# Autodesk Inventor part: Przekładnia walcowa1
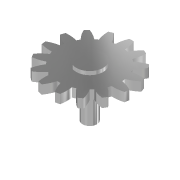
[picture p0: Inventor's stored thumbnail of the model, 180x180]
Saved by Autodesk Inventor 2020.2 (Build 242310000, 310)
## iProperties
Manager: www.cadconsulting.pl
Company: Fabian Stasiak CAD Consulting
CustomPartVersion: 1
Created: 2014-10
Part Number: Przekładnia walcowa1
Material: Steel
Document SubType Name: Modeling
Designer: F.Stasiak
Categories: <?xml version="1.0" encoding="UTF-16"?> <MemberInstance><Categories><FamilyTemplate><FamilyTemplateParameter ValueType="xs:double" Id="1" ObjectReferenceKey="da
Density: 7.85 g/cm^3
Appearance: Chrom - polerowany
Mass: 65.8697 g
Surface Area: 46.5032 cm^2
Volume: 8.39104 cm^3
Catalog Web Link: www.expertbooks.pl
Author: F.Stasiak
Subject: Zbiór ćwiczeń. Autodesk Inventor 2020. Kurs Professional
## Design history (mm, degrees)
sketch "Sketch1"
  geometry: C1 r 23.359 at (0, 0)
  constraints: 1 centre point
  dimensions: "d0" = 46.7178 diameter of C1 (= da_da)
extrude "Extrusion1" new body sketch "Sketch1" distance "d1" = 5 (= da_b); taper "d2" = 0 deg
workplane "Work Plane2"
sketch "Sketch2"
  geometry: C1 r 23.359 at (0, 0) reference; C2 r 20.745 at (0, 0)
  constraints: 1 centre point, 1 coincident
  dimensions: "d3" = 41.48936 diameter of C2 (= da_dw)
feature "Średnica podziałowa" sketch "Sketch2" dims "d4" = 10, "d5" = 0
workplane "Work Plane8"
workplane "Work Plane9"
feature "Przekładnia walcowa" dims "da_b" = 5, "da_d" = 41.25, "da_aw" = 130, "da_da" = 46.7178, "da_df" = 34.375, "da_dw" = 41.48936, angle "da_beta" = 0 deg, "da_lefttooth" = 0, "da_righttooth" = 0
sketch "Szkic3"
  geometry: C1 r 7.5 at (0, 0); 1 further point
  constraints: 1 centre point, 1 coincident
  dimensions: "d49" = 15 diameter of C1
extrude "Wyciągnięcie proste2" join sketch "Szkic3" distance "d50" = 2; taper "d51" = 0 deg
sketch "Szkic4"
  geometry: C1 r 8 at (0, 0); 1 further point
  constraints: 1 centre point, 1 coincident
  dimensions: "d52" = 16 diameter of C1
extrude "Wyciągnięcie proste3" join sketch "Szkic4" distance "d53" = 2; taper "d54" = 0 deg
sketch "Szkic5"
  geometry: C1 r 4 at (0, 0); 1 further point
  constraints: 1 centre point, 1 coincident
  dimensions: "d55" = 8 diameter of C1
extrude "Wyciągnięcie proste4" join sketch "Szkic5" distance "d56" = 20; taper "d57" = 0 deg
body "Solid1"
body "Srf1"
other parameters: "d17" = 0, "d34" = 12 deg (computed from da_z), "d39" = 0, "d41" = 0, "d47" = 0, "d48" = 0
